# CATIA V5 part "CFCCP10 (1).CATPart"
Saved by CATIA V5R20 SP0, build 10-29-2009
Part number: CFCCP10 (1)
Revision: TUTTO
Definition: NON CONOSCIUTO
Nomenclature: CFCCP10 (1)
Source: Unknown
Bounding box of the stored display mesh (mm): x -50 to 50, y -50 to 50, z -55 to 0
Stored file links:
  C:\Users\Utente\Desktop\IO LAVORO\3D X SITO CF\X 3D SITO CF 27-09-2020\CFCCP\CFCCP10 (1).CATPart
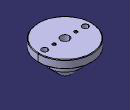
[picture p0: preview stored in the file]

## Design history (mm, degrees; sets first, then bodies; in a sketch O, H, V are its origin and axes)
Body1 "Foro filettato M5-1" (main body)
  Solid1: solid without history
